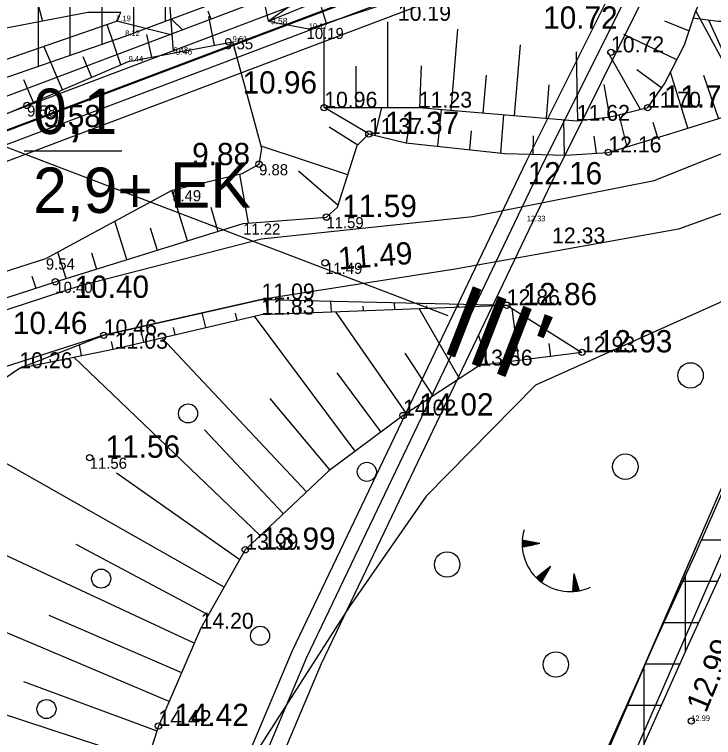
# Model space of a CAD drawing. Extents: x 433497 to 434382, y 6534486 to 6534993.
# Drawn here: x 434093.7 to 434137.69, y 6534741.61 to 6534787.09 of the extents above; entities that cross this region are included whole.
import ezdxf

# ---------------------------------------------------------------- set-up
doc = ezdxf.new("R2010")
doc.units = 0
for name, color, linetype in [('Default', 7, 'Continuous'), ('GEOLPUNKT', 7, 'Continuous'), ('HALJASTUS', 7, 'Continuous'), ('Kaitsevöönd', 7, 'Continuous'), ('kataster', 7, 'Continuous'), ('KORGUS-EH2000', 7, 'Continuous'), ('l__x00e4__bil__x00f5__iked', 7, 'Continuous'), ('MAAMUDEL-EH2000', 7, 'Continuous'), ('MOOTKORG-EH2000', 7, 'Continuous'), ('PIIR', 7, 'Continuous'), ('RELJEEF', 7, 'Continuous'), ('TEE', 7, 'Continuous'), ('Täide', 7, 'Continuous'), ('VEEKOGU', 7, 'Continuous')]:
    doc.layers.add(name, color=color, linetype=linetype)

msp = doc.modelspace()

# ---------------------------------------------------------------- linework, layer by layer
at = {"layer": 'Default'}
msp.add_lwpolyline([(433617.12, 6534791.025), (433632.75, 6534606.045), (434137.38, 6534796.515), (434127.69, 6534855.6), (433968.21, 6534911.925), (433942.38, 6534904.035), (433920.99, 6534907.275)], close=True, dxfattribs=at)
msp.add_lwpolyline([(433617.12, 6534791.025), (433632.75, 6534606.045), (434137.38, 6534796.515), (434127.69, 6534855.6), (433968.21, 6534911.925), (433942.38, 6534904.035), (433920.99, 6534907.275)], close=True, dxfattribs=at)
msp.add_lwpolyline([(433617.12, 6534791.025), (433632.75, 6534606.045), (434137.38, 6534796.515), (434127.69, 6534855.6), (433968.21, 6534911.925), (433942.38, 6534904.035), (433920.99, 6534907.275)], close=True, dxfattribs=at)
at = {"layer": 'GEOLPUNKT'}
msp.add_lwpolyline([(434094.323, 6534778.51), (434100.451, 6534778.51)], dxfattribs=at)
at = {"layer": 'HALJASTUS'}
msp.add_lwpolyline([(434120.167, 6534715.22), (434123.286, 6534722.97), (434138.264, 6534757.493), (434144.614, 6534770.457), (434146.069, 6534772.243), (434145.275, 6534773.036), (434138, 6534768.935), (434126.491, 6534763.776), (434119.612, 6534756.789), (434114.784, 6534749.844), (434107.728, 6534738.859), (434104.135, 6534730.068), (434101.605, 6534722.143)], dxfattribs=at)
for centre, radius in [((434136.24, 6534764.387), 0.8), ((434104.627, 6534761.996), 0.6), ((434132.139, 6534758.646), 0.8), ((434115.876, 6534758.324), 0.6), ((434120.929, 6534752.494), 0.8), ((434099.159, 6534751.606), 0.6), ((434109.158, 6534748.012), 0.6), ((434127.764, 6534746.205), 0.8), ((434095.722, 6534743.403), 0.6)]:
    msp.add_circle(centre, radius, dxfattribs=at)
at = {"layer": 'Kaitsevöönd'}
for p, q in [((434136.931, 6534754.039), (434139.114, 6534754.039)), ((434135.931, 6534747.021), (434135.931, 6534751.819)), ((434135.756, 6534751.439), (434137.957, 6534751.439)), ((434134.563, 6534748.839), (434136.763, 6534748.839)), ((434133.331, 6534741.222), (434133.331, 6534746.11)), ((434133.389, 6534746.239), (434135.58, 6534746.239)), ((434132.223, 6534743.639), (434134.415, 6534743.639))]:
    msp.add_line(p, q, dxfattribs=at)
for points in [[(434128.222, 6534730.093), (434132.174, 6534738.642), (434136.032, 6534747.247), (434138.365, 6534752.329), (434142.93, 6534762.753), (434145.458, 6534769.142), (434146.369, 6534771.613), (434148.646, 6534776.777), (434150.916, 6534781.958), (434153.219, 6534787.206), (434154.721, 6534791.754), (434156.628, 6534795.899), (434159.877, 6534804.556), (434163.808, 6534814.841), (434168.182, 6534825.411), (434171.941, 6534834.072), (434175.51, 6534841.483), (434180.59, 6534850.694), (434185.974, 6534861.252), (434188.694, 6534866.232), (434193.777, 6534875.182), (434200.729, 6534887.95), (434203.323, 6534892.681)], [(434198.974, 6534888.909), (434192.024, 6534876.146), (434186.943, 6534867.198), (434184.199, 6534862.173), (434178.816, 6534851.617), (434173.72, 6534842.375), (434170.114, 6534834.886), (434166.338, 6534826.183), (434161.945, 6534815.568), (434158.005, 6534805.262), (434154.768, 6534796.635), (434152.881, 6534792.54), (434152.839, 6534792.435), (434151.335, 6534787.878), (434149.085, 6534782.762), (434146.815, 6534777.582), (434144.503, 6534772.334), (434143.585, 6534769.845), (434141.077, 6534763.506), (434136.537, 6534753.14), (434134.209, 6534748.069), (434130.352, 6534739.465)]]:
    msp.add_lwpolyline(points, dxfattribs=at)
at = {"layer": 'kataster'}
msp.add_lwpolyline([(433617.102, 6534791.002), (433632.769, 6534606.029), (434137.446, 6534796.469), (434127.827, 6534855.589), (433950.026, 6534918.39)], close=True, dxfattribs=at)
msp.add_lwpolyline([(434117.185, 6534708.296), (434124.427, 6534725.502), (434148.55, 6534781.242), (434178.983, 6534849.691), (434202.394, 6534892.23)], dxfattribs=at)
at = {"layer": 'KORGUS-EH2000'}
for centre in [(434131.23, 6534784.703), (434094.496, 6534781.369), (434113.19, 6534781.228), (434133.547, 6534781.228), (434116.003, 6534779.573), (434131.064, 6534778.414), (434109.094, 6534777.673), (434113.333, 6534774.346), (434113.249, 6534771.472), (434096.278, 6534770.278), (434124.677, 6534768.804), (434099.32, 6534766.909), (434129.409, 6534765.836), (434118.155, 6534761.864), (434098.439, 6534759.213), (434108.225, 6534753.423), (434136.29, 6534742.65), (434102.763, 6534742.334)]:
    msp.add_circle(centre, 0.2, dxfattribs=at)
at = {"layer": 'l__x00e4__bil__x00f5__iked'}
msp.add_lwpolyline([(433837.129, 6534901.88), (433863.279, 6534885.992), (433986.579, 6534812.177), (434090.185, 6534779.904), (434120.969, 6534768.153)], dxfattribs=at)
at = {"layer": 'PIIR'}
for points in [[(433632.021, 6534604.835), (434138.248, 6534795.936), (434128.468, 6534856.135), (433968.226, 6534912.818), (433942.33, 6534904.85), (433920.952, 6534908.165), (433616.327, 6534791.524), (433632.021, 6534604.835)], [(433632.732, 6534605.959), (434137.353, 6534796.454), (434127.754, 6534855.539), (433968.208, 6534911.976), (433942.39, 6534904.031), (433921.04, 6534907.341), (433617.174, 6534790.992), (433632.732, 6534605.959)], [(434096.984, 6534713.464), (434111.196, 6534747.086), (434125.923, 6534777.863), (434134.171, 6534794.397)], [(434098.826, 6534712.686), (434113.02, 6534746.265), (434127.72, 6534776.985), (434136.477, 6534794.54)], [(433633.446, 6534604.304), (434134.891, 6534793.6)], [(434097.905, 6534713.075), (434112.108, 6534746.676), (434126.821, 6534777.424), (434134.891, 6534793.6)]]:
    msp.add_lwpolyline(points, dxfattribs=at)
for points in [[(433618.234, 6534790.327), (433921.149, 6534906.313), (433942.464, 6534903.008), (433968.187, 6534910.923), (434126.862, 6534854.794), (434136.235, 6534797.101), (433633.617, 6534607.362)], [(433619.24, 6534789.695), (433634.52, 6534608.851), (434135.141, 6534797.808), (434125.908, 6534854.108), (433968.165, 6534909.82), (433942.53, 6534901.99), (433921.212, 6534905.219)], [(433619.24, 6534789.695), (433634.52, 6534608.851), (434135.141, 6534797.808), (434125.908, 6534854.108), (433968.165, 6534909.82), (433942.53, 6534901.99), (433921.212, 6534905.219)]]:
    msp.add_lwpolyline(points, close=True, dxfattribs=at)
at = {"layer": 'RELJEEF'}
for p, q in [((434094.442, 6534790.499), (434095.475, 6534786.664)), ((434113.009, 6534787.553), (434113.309, 6534786.54)), ((434105.873, 6534787.316), (434106.037, 6534786.852)), ((434105.918, 6534786.956), (434106.261, 6534785.152)), ((434139.86, 6534781.218), (434136.58, 6534787.318)), ((434103.62, 6534785.793), (434100.118, 6534786.667)), ((434104.277, 6534786.117), (434103.597, 6534786.782)), ((434117.19, 6534781.228), (434117.195, 6534786.632)), ((434134.591, 6534786.679), (434136.158, 6534786.064)), ((434139.86, 6534781.218), (434137.387, 6534786.725)), ((434100.4, 6534783.921), (434099.544, 6534786.468)), ((434113.19, 6534781.228), (434113.19, 6534786.267)), ((434121.183, 6534781.058), (434121.609, 6534786.171)), ((434102.016, 6534785.839), (434102.332, 6534784.404)), ((434135.378, 6534784.229), (434132.049, 6534785.832)), ((434125.169, 6534780.726), (434125.539, 6534785.169)), ((434096.721, 6534782.35), (434095.553, 6534785.087)), ((434129.155, 6534780.409), (434129.063, 6534784.747)), ((434133.085, 6534781.114), (434131.055, 6534784.707)), ((434098.004, 6534784.439), (434098.561, 6534783.136)), ((434115.19, 6534783.838), (434115.19, 6534781.228)), ((434119.302, 6534783.864), (434119.19, 6534781.224)), ((434132.861, 6534783.633), (434134.427, 6534782.472)), ((434136.079, 6534779.936), (434134.985, 6534783.465)), ((434094.27, 6534782.998), (434094.882, 6534781.565)), ((434123.374, 6534783.268), (434123.176, 6534780.892)), ((434137.062, 6534783.265), (434137.988, 6534780.533)), ((434127.33, 6534782.669), (434127.162, 6534780.56)), ((434130.776, 6534782.682), (434131.141, 6534780.644)), ((434116.402, 6534779.476), (434116.826, 6534781.228)), ((434120.335, 6534778.797), (434120.579, 6534781.108)), ((434124.313, 6534778.377), (434124.483, 6534780.783)), ((434132.252, 6534778.772), (434131.741, 6534780.784)), ((434118.538, 6534780.117), (434118.346, 6534779.006)), ((434128.31, 6534778.25), (434128.275, 6534780.467)), ((434133.874, 6534780.312), (434134.167, 6534779.348)), ((434113.509, 6534780.027), (434115.318, 6534778.897)), ((434122.448, 6534779.764), (434122.324, 6534778.587)), ((434126.348, 6534779.464), (434126.311, 6534778.304)), ((434130.164, 6534779.439), (434130.306, 6534778.367)), ((434114.684, 6534777.008), (434109.22, 6534778.799)), ((434108.425, 6534773.963), (434107.893, 6534777.055)), ((434111.565, 6534777.255), (434114.074, 6534775.103)), ((434104.59, 6534772.853), (434103.607, 6534776.028)), ((434106.057, 6534774.978), (434106.501, 6534773.445)), ((434100.769, 6534771.669), (434100.02, 6534774.09)), ((434102.246, 6534773.66), (434102.68, 6534772.261)), ((434096.949, 6534770.486), (434096.426, 6534772.148)), ((434098.543, 6534772.099), (434098.859, 6534771.078)), ((434094.801, 6534770.632), (434095.043, 6534769.878)), ((434109.644, 6534768.228), (434109.537, 6534769.159)), ((434113.641, 6534768.381), (434113.615, 6534769.063)), ((434115.629, 6534768.737), (434115.639, 6534768.458)), ((434117.638, 6534768.534), (434117.621, 6534768.969)), ((434119.63, 6534768.767), (434119.636, 6534768.611)), ((434121.635, 6534768.688), (434121.628, 6534768.876)), ((434123.637, 6534768.796), (434123.634, 6534768.764)), ((434105.738, 6534767.398), (434105.523, 6534768.318)), ((434107.588, 6534768.308), (434107.686, 6534767.851)), ((434111.627, 6534768.707), (434111.642, 6534768.305)), ((434118.36, 6534761.998), (434113.921, 6534768.392)), ((434121.706, 6534764.19), (434119.166, 6534768.593)), ((434125.442, 6534765.327), (434125.024, 6534768.587)), ((434115.147, 6534759.618), (434108.805, 6534768.111)), ((434101.842, 6534766.491), (434101.624, 6534767.432)), ((434103.681, 6534767.41), (434103.79, 6534766.945)), ((434099.79, 6534766.517), (434099.893, 6534766.042)), ((434112.083, 6534757.056), (434102.983, 6534766.757)), ((434122.901, 6534766.894), (434123.458, 6534765.073)), ((434097.933, 6534765.642), (434097.796, 6534766.315)), ((434127.321, 6534766.396), (434127.426, 6534765.581)), ((434118.266, 6534765.792), (434120.033, 6534763.094)), ((434129.409, 6534765.836), (434129.409, 6534765.836)), ((434095.939, 6534765.41), (434095.974, 6534765.242)), ((434109.171, 6534754.314), (434097.432, 6534765.54)), ((434113.981, 6534764.551), (434116.749, 6534760.814)), ((434109.766, 6534762.939), (434113.544, 6534758.421)), ((434106.893, 6534751.073), (434089.95, 6534760.674)), ((434105.664, 6534760.955), (434110.627, 6534755.685)), ((434100.124, 6534758.27), (434107.879, 6534752.813)), ((434105.017, 6534747.546), (434088.397, 6534755.272)), ((434097.573, 6534753.767), (434105.907, 6534749.333)), ((434125.641, 6534753.828), (434125.84, 6534753.987)), ((434125.641, 6534753.764), (434125.904, 6534753.975)), ((434125.642, 6534753.893), (434125.776, 6534754)), ((434125.643, 6534753.701), (434125.969, 6534753.962)), ((434125.645, 6534753.959), (434125.711, 6534754.012)), ((434125.646, 6534753.64), (434126.033, 6534753.95)), ((434126.761, 6534753.809), (434125.648, 6534754.024)), ((434126.761, 6534753.809), (434125.649, 6534753.591)), ((434125.67, 6534753.595), (434126.098, 6534753.937)), ((434125.776, 6534753.616), (434126.162, 6534753.925)), ((434125.882, 6534753.636), (434126.227, 6534753.912)), ((434125.988, 6534753.657), (434126.291, 6534753.9)), ((434126.094, 6534753.678), (434126.356, 6534753.888)), ((434126.2, 6534753.699), (434126.42, 6534753.875)), ((434126.306, 6534753.72), (434126.485, 6534753.863)), ((434126.412, 6534753.741), (434126.549, 6534753.85)), ((434126.518, 6534753.761), (434126.613, 6534753.838)), ((434126.624, 6534753.782), (434126.678, 6534753.825)), ((434127.425, 6534752.369), (434126.537, 6534751.665)), ((434127.425, 6534752.369), (434126.866, 6534751.383)), ((434126.827, 6534751.413), (434126.844, 6534751.908)), ((434126.876, 6534751.401), (434126.895, 6534751.949)), ((434126.93, 6534751.495), (434126.947, 6534751.99)), ((434126.983, 6534751.589), (434126.998, 6534752.031)), ((434127.036, 6534751.683), (434127.05, 6534752.071)), ((434127.09, 6534751.777), (434127.101, 6534752.112)), ((434127.143, 6534751.871), (434127.153, 6534752.153)), ((434127.196, 6534751.965), (434127.204, 6534752.194)), ((434127.25, 6534752.059), (434127.256, 6534752.234)), ((434127.303, 6534752.153), (434127.307, 6534752.275)), ((434127.356, 6534752.247), (434127.359, 6534752.316)), ((434128.89, 6534751.921), (434128.805, 6534750.79)), ((434128.89, 6534751.921), (434129.235, 6534750.841)), ((434126.584, 6534751.619), (434126.587, 6534751.704)), ((434126.632, 6534751.574), (434126.638, 6534751.745)), ((434126.681, 6534751.531), (434126.69, 6534751.786)), ((434126.729, 6534751.49), (434126.741, 6534751.827)), ((434126.778, 6534751.451), (434126.793, 6534751.868)), ((434129.097, 6534751.273), (434128.859, 6534751.508)), ((434129.064, 6534751.376), (434128.864, 6534751.574)), ((434129.031, 6534751.479), (434128.869, 6534751.639)), ((434128.998, 6534751.582), (434128.874, 6534751.705)), ((434128.965, 6534751.684), (434128.879, 6534751.77)), ((434128.933, 6534751.787), (434128.883, 6534751.836)), ((434129.064, 6534750.813), (434128.825, 6534751.05)), ((434129.126, 6534750.822), (434128.829, 6534751.116)), ((434129.187, 6534750.832), (434128.834, 6534751.181)), ((434129.229, 6534750.861), (434128.839, 6534751.247)), ((434129.196, 6534750.964), (434128.844, 6534751.312)), ((434129.163, 6534751.067), (434128.849, 6534751.378)), ((434129.13, 6534751.17), (434128.854, 6534751.443)), ((434103.429, 6534743.874), (434086.728, 6534750.95)), ((434128.87, 6534750.794), (434128.81, 6534750.854)), ((434128.936, 6534750.799), (434128.815, 6534750.919)), ((434129.001, 6534750.806), (434128.82, 6534750.985)), ((434095.876, 6534749.319), (434104.223, 6534745.71)), ((434102.041, 6534740.127), (434085.333, 6534745.592)), ((434094.273, 6534745.136), (434102.663, 6534742.028))]:
    msp.add_line(p, q, dxfattribs=at)
for points in [[(434002.621, 6534891.199), (434008.357, 6534898.477), (434008.844, 6534898.428), (434009.684, 6534897.899), (434020.673, 6534893.319), (434025.184, 6534891.367), (434026.4, 6534888.82), (434028.53, 6534881.31), (434029.71, 6534869.667), (434036.879, 6534848.772), (434040.385, 6534828.949), (434036.914, 6534815.456), (434039.48, 6534802.82), (434040.271, 6534794.377), (434046.22, 6534786.31), (434052.87, 6534782.4), (434066.43, 6534782.05), (434080.61, 6534786.771), (434096.029, 6534790.927), (434100.314, 6534792.082), (434103.079, 6534792.827), (434103.7, 6534784.75)], [(434116.003, 6534779.573), (434118.33, 6534779.008), (434124.552, 6534778.351), (434128.388, 6534778.248), (434131.064, 6534778.414), (434134.99, 6534779.596), (434139.415, 6534780.978), (434142.65, 6534782.717), (434146.846, 6534785.714), (434149.957, 6534788.306), (434152.414, 6534790.827), (434154.555, 6534795.185), (434159.2, 6534807.543), (434167.641, 6534827.734), (434175.75, 6534844.947), (434185.846, 6534863.98), (434196.935, 6534884.171), (434200.713, 6534891.388)], [(434116.003, 6534779.573), (434118.33, 6534779.008), (434124.552, 6534778.351), (434128.388, 6534778.248), (434131.064, 6534778.414), (434134.99, 6534779.596), (434139.415, 6534780.978), (434142.65, 6534782.717), (434146.846, 6534785.714), (434149.957, 6534788.306), (434152.414, 6534790.827), (434154.555, 6534795.185), (434159.2, 6534807.543), (434167.641, 6534827.734), (434175.75, 6534844.947), (434185.846, 6534863.98), (434196.935, 6534884.171)], [(434113.19, 6534781.228), (434119.148, 6534781.228), (434129.078, 6534780.4), (434131.196, 6534780.65), (434133.547, 6534781.228), (434134.6, 6534782.717), (434135.868, 6534785.182), (434136.526, 6534787.186), (434139.174, 6534793.64), (434143.477, 6534801.419), (434147.284, 6534810.522), (434153.573, 6534824.093), (434156.717, 6534837.003), (434157.71, 6534847.595)], [(434109.687, 6534786.673), (434112.222, 6534786.179), (434118.757, 6534788.35), (434129.51, 6534792.559), (434134.019, 6534795.71), (434135.253, 6534797.374), (434140.289, 6534808.003), (434143.311, 6534815.613)], [(434109.687, 6534786.673), (434117.282, 6534789.783), (434131.587, 6534795.543), (434133.62, 6534797.699), (434138.093, 6534806.728), (434141.209, 6534813.9)], [(434133.62, 6534797.699), (434131.587, 6534795.543), (434125.259, 6534793.878), (434114.603, 6534790.134), (434109.687, 6534786.673), (434109.111, 6534789.39), (434108.205, 6534793.713)], [(434140.664, 6534786.689), (434139.309, 6534786.65), (434137.986, 6534786.65), (434136.36, 6534786.855)], [(434042.383, 6534754.563), (434049.423, 6534756.289), (434054.343, 6534758.291), (434054.765, 6534763.79), (434062.713, 6534768.089), (434076.377, 6534773.391), (434084.66, 6534777.201), (434100.89, 6534784.13), (434107.434, 6534785.375)], [(434081.64, 6534765.873), (434081.64, 6534765.873), (434084.665, 6534768.217), (434095.679, 6534771.744), (434103.625, 6534776.038), (434108.041, 6534777.09), (434109.094, 6534777.673), (434109.26, 6534778.654), (434107.434, 6534785.375)], [(434116.003, 6534779.573), (434113.19, 6534781.228)], [(434081.64, 6534765.873), (434084.95, 6534766.611), (434096.278, 6534770.278), (434108.089, 6534773.937), (434113.333, 6534774.346), (434114.03, 6534774.964), (434115.274, 6534778.854), (434116.003, 6534779.573)], [(434094.014, 6534764.842), (434099.32, 6534766.909), (434109.25, 6534769.165), (434124.677, 6534768.804)], [(434094.014, 6534764.842), (434100.012, 6534766.066), (434109.24, 6534768.212), (434124.677, 6534768.804), (434129.409, 6534765.836)], [(434129.409, 6534765.836), (434122.955, 6534765.008), (434118.155, 6534761.864), (434113.491, 6534758.381), (434108.225, 6534753.423), (434105.411, 6534748.458), (434102.763, 6534742.334), (434096.971, 6534724.625)], [(434078.765, 6534722.143), (434083.764, 6534734.729), (434085.385, 6534739.19), (434085.147, 6534744.27), (434085.551, 6534747.134), (434086.598, 6534750.63), (434088.199, 6534754.582), (434090.453, 6534762.425), (434094.014, 6534764.842)]]:
    msp.add_lwpolyline(points, dxfattribs=at)
msp.add_arc((434128.668, 6534753.814), 3.027, 163.4234, 295.1745, dxfattribs=at)
at = {"layer": 'TEE'}
for points in [[(434079.751, 6534762.916), (434087.895, 6534766.788), (434097.926, 6534770.058), (434097.976, 6534770.078), (434098.026, 6534770.088), (434098.086, 6534770.108), (434109.24, 6534772.987), (434122.531, 6534774.391), (434133.956, 6534776.648), (434144.207, 6534780.731), (434144.327, 6534780.781)], [(434145.12, 6534777.059), (434135.48, 6534773.589), (434121.427, 6534771.071), (434109.25, 6534769.165), (434099.32, 6534766.909), (434088.868, 6534763.558), (434081.095, 6534760.008)], [(434119.091, 6534708.897), (434123.118, 6534718.63), (434123.124, 6534718.644), (434123.131, 6534718.659), (434123.138, 6534718.676), (434134.061, 6534743.666), (434144.319, 6534767.161), (434146.018, 6534771.113)]]:
    msp.add_lwpolyline(points, dxfattribs=at)
at = {"layer": 'Täide'}
for p, q in [((434095.213, 6534783.838), (434095.213, 6534863.203)), ((434097.213, 6534784.532), (434097.213, 6534862.448)), ((434099.213, 6534785.226), (434099.213, 6534861.785)), ((434101.213, 6534785.934), (434101.213, 6534861.198)), ((434103.213, 6534786.679), (434103.213, 6534860.611))]:
    msp.add_line(p, q, dxfattribs=at)
msp.add_lwpolyline([(434053.953, 6534766.741), (434062.043, 6534770.897), (434076.601, 6534775.79), (434083.107, 6534779.636), (434100.67, 6534785.732), (434110.817, 6534789.511), (434130.115, 6534796.22), (434132.899, 6534799.258), (434133.017, 6534809.88), (434125.182, 6534852.548), (434123.278, 6534854.722), (434098.113, 6534862.108), (434062.901, 6534875.407), (434022.093, 6534888.443), (434021.059, 6534887.256), (434037.893, 6534864.165), (434021.392, 6534791.18), (434023.3, 6534781.148), (434025.663, 6534773.898), (434039.607, 6534770.357), (434045.083, 6534767.989), (434045.714, 6534765.502), (434044.882, 6534761.539)], dxfattribs=at)
at = {"layer": 'VEEKOGU'}
for points in [[(434100.405, 6534787.207), (434098.317, 6534787.207), (434089.545, 6534785.531), (434086.602, 6534783.735), (434074.461, 6534779.832), (434066.338, 6534777.192), (434050.88, 6534777.91), (434044.67, 6534782.72), (434037.09, 6534794.99), (434032.35, 6534809.44), (434034.87, 6534823.21), (434035.905, 6534837.207), (434031.53, 6534853.98), (434027.762, 6534864.072)], [(434050.128, 6534758.038), (434051.667, 6534760.055), (434049.568, 6534761.922), (434050.115, 6534764.979), (434053.54, 6534767.639), (434061.885, 6534771.617), (434075.613, 6534776.761), (434082.778, 6534780.666), (434100.118, 6534786.667), (434100.405, 6534787.207)]]:
    msp.add_lwpolyline(points, dxfattribs=at)

# ---------------------------------------------------------------- texts
at = {"layer": 'GEOLPUNKT'}
for s, p in [('0,1', (434094.881, 6534779.573)), ('2,9+', (434094.881, 6534774.607)), ('EK', (434103.487, 6534774.939))]:
    msp.add_text(s, height=2.85, dxfattribs=at).set_placement(p)
at = {"layer": 'KORGUS-EH2000'}
for s, p in [('10.72', (434126.966, 6534786.195)), ('10.96', (434108.056, 6534782.115)), ('11.70', (434134.547, 6534781.228)), ('9.58', (434095.496, 6534780.001)), ('11.37', (434117.003, 6534779.573)), ('9.88', (434104.884, 6534777.61)), ('12.16', (434125.994, 6534776.403)), ('11.59', (434114.333, 6534774.346)), ('10.40', (434097.485, 6534769.266)), ('12.86', (434125.677, 6534768.804)), ('10.46', (434093.606, 6534766.991)), ('12.93', (434130.409, 6534765.836)), ('14.02', (434119.155, 6534761.864)), ('11.56', (434099.439, 6534759.213)), ('13.99', (434109.225, 6534753.423)), ('14.42', (434103.763, 6534742.334))]:
    msp.add_text(s, height=1.4, dxfattribs=at).set_placement(p)
for s, rotation, p in [('11.49', 4.5238, (434114.122, 6534771.038)), ('12.99', 67.627, (434137.212, 6534743.115))]:
    msp.add_text(s, height=1.4, rotation=rotation, dxfattribs=at).set_placement(p)
at = {"layer": 'l__x00e4__bil__x00f5__iked'}
msp.add_text("III'", height=4.58, rotation=338.8439, dxfattribs=at).set_placement((434120.361, 6534765.927))
at = {"layer": 'MAAMUDEL-EH2000'}
for s, p in [(' 9.58', (434109.687, 6534786.473)), (' 9.46', (434103.7, 6534784.55))]:
    msp.add_text(s, height=0.4, dxfattribs=at).set_placement(p)
at = {"layer": 'MOOTKORG-EH2000'}
for s, height, p in [('10.19', 1, (434117.824, 6534786.689)), ('7.19', 0.35, (434100.118, 6534786.667)), ('10.17', 0.35, (434112.222, 6534786.179)), ('8.12', 0.35, (434100.67, 6534785.732)), ('10.19', 0.7, (434112.083, 6534785.546)), ('9.55', 0.7, (434106.9, 6534784.898)), ('9.61', 0.35, (434107.434, 6534785.375)), ('10.72', 1, (434131.23, 6534784.703)), ('9.42', 0.35, (434103.717, 6534784.686)), ('9.44', 0.35, (434100.89, 6534784.13)), ('10.96', 1, (434113.19, 6534781.228)), ('11.23', 1, (434119.148, 6534781.228)), ('11.70', 1, (434133.547, 6534781.228)), ('9.58', 0.7, (434094.496, 6534780.669)), ('11.62', 1, (434129.078, 6534780.4)), ('11.37', 1, (434116.003, 6534779.573)), ('12.16', 1, (434131.064, 6534778.414)), ('9.88', 0.7, (434109.094, 6534776.973)), ('9.49', 0.7, (434103.625, 6534775.338)), ('11.59', 0.7, (434113.333, 6534773.646)), ('12.33', 0.35, (434125.94, 6534774.08)), ('11.22', 0.7, (434108.089, 6534773.237)), ('12.33', 1, (434127.526, 6534772.686)), ('9.54', 0.7, (434095.679, 6534771.044)), ('11.49', 0.7, (434113.249, 6534770.772)), ('10.40', 0.7, (434096.278, 6534769.578)), ('11.09', 1, (434109.25, 6534769.165)), ('12.86', 1, (434124.677, 6534768.804)), ('11.83', 1, (434109.24, 6534768.212)), ('10.46', 1, (434099.32, 6534766.909)), ('11.03', 1, (434100.012, 6534766.066)), ('12.93', 1, (434129.409, 6534765.836)), ('13.56', 1, (434122.955, 6534765.008)), ('10.26', 1, (434094.014, 6534764.842)), ('14.02', 1, (434118.155, 6534761.864)), ('11.56', 0.7, (434098.439, 6534758.513)), ('13.99', 1, (434108.225, 6534753.423)), ('14.20', 1, (434105.411, 6534748.458)), ('14.42', 1, (434102.763, 6534742.334)), ('12.99', 0.35, (434136.29, 6534742.65))]:
    msp.add_text(s, height=height, dxfattribs=at).set_placement(p)

doc.saveas('drawing.dxf')
